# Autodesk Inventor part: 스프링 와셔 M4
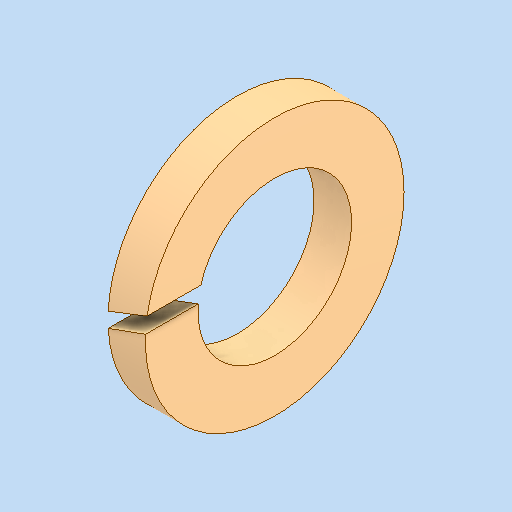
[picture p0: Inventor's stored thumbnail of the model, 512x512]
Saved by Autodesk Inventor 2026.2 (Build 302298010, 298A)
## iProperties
Created: 2026-03
Part Number: 스프링 와셔 M4
Material: 강철, 연강
Description: 스프링 잠금 와셔
Document SubType Name: Modeling
Designer: PC-2-03
Density: 7.85 g/cm^3
Appearance: 기본값
Author: jhkim
Sending System: Autodesk Inventor 2026
Preprocessor: ST-DEVELOPER v20.1
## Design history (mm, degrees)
feature "Solid1"
node "솔리드1"
